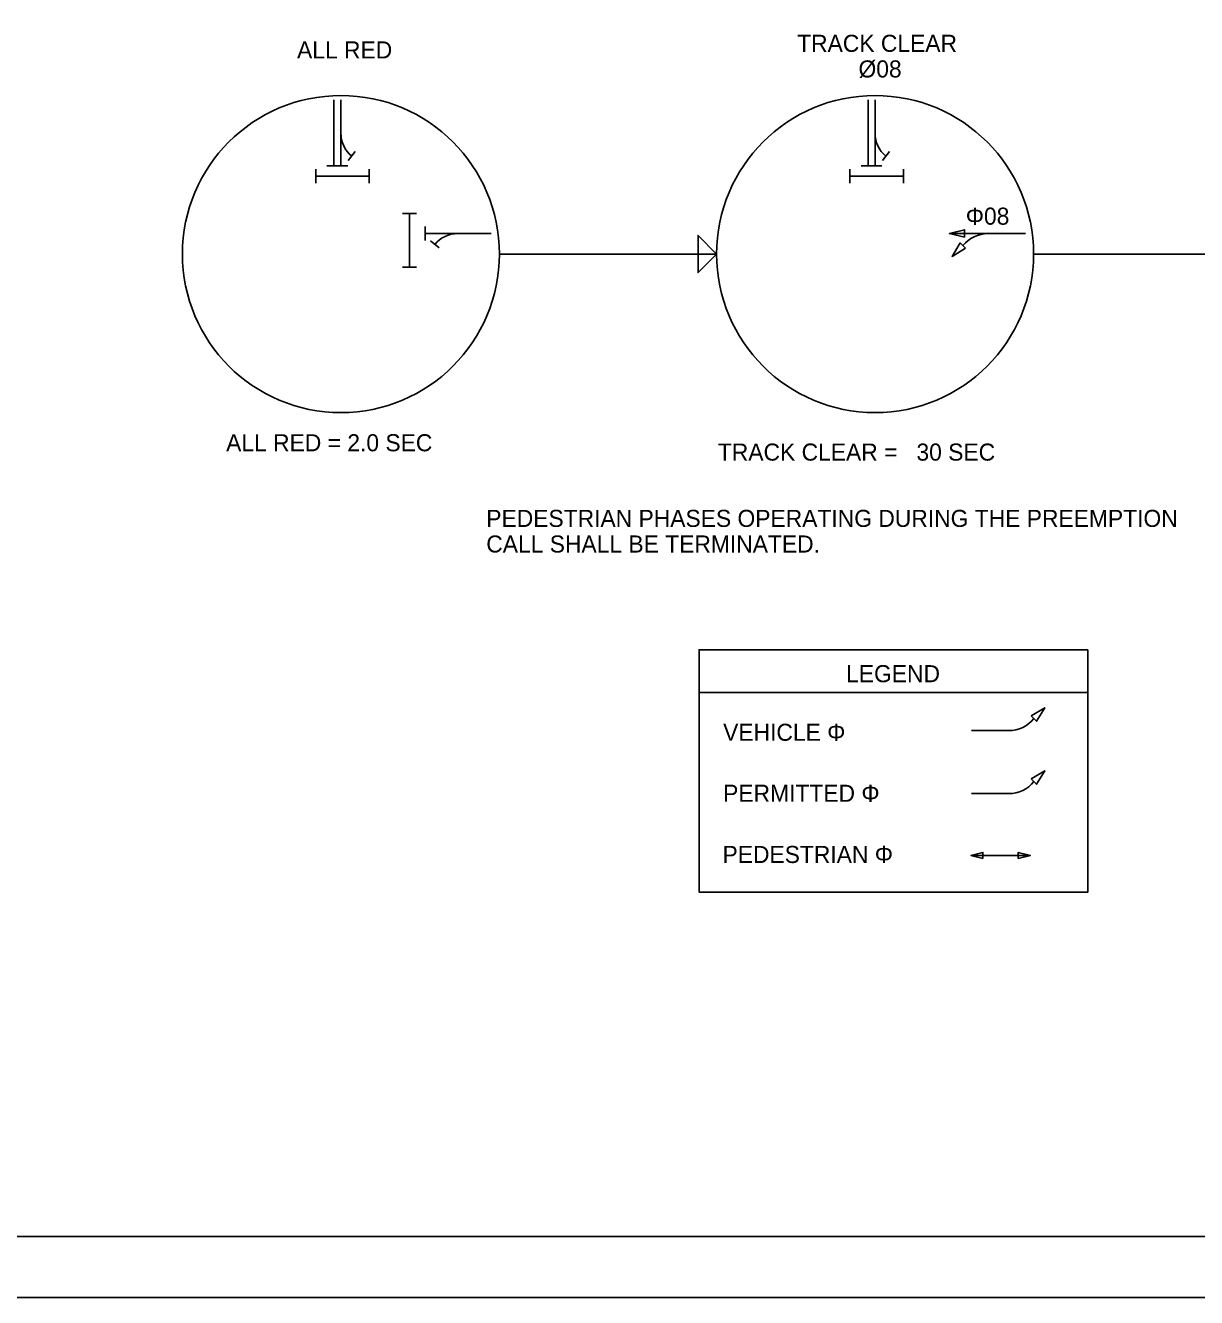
# Model space of a CAD drawing. Extents: x 0 to 680, y 0 to 440.
# Drawn here: x 340 to 532, y 0 to 208.6 of the extents above; entities that cross this region are included whole.
import ezdxf

# ---------------------------------------------------------------- set-up
doc = ezdxf.new("R2010")
doc.units = 0
for name, color, linetype in [('SG_P_Text', 7, 'Continuous'), ('SH_Border', 7, 'Continuous'), ('SH_Cut_Line', 7, 'Continuous'), ('SH_Data', 7, 'Continuous'), ('SH_Text', 7, 'Continuous')]:
    doc.layers.add(name, color=color, linetype=linetype)

msp = doc.modelspace()

# ---------------------------------------------------------------- linework, layer by layer
at = {"layer": 'SG_P_Text'}
for p, q in [((390.58, 196.38), (390.58, 185.57)), ((391.72, 196.38), (391.72, 185.57)), ((391.72, 196.38), (391.72, 190.88)), ((478.18, 196.38), (478.18, 185.57)), ((479.32, 196.38), (479.32, 185.57)), ((479.32, 196.38), (479.32, 190.88)), ((392.92, 186.45), (394.08, 187.88)), ((480.53, 186.45), (481.68, 187.88)), ((387.61, 184.99), (387.61, 182.71)), ((387.61, 183.85), (396.38, 183.85)), ((389.44, 185.57), (391.72, 185.57)), ((390.58, 185.57), (392.86, 185.57)), ((396.38, 184.99), (396.38, 182.71)), ((475.21, 184.99), (475.21, 182.71)), ((475.21, 183.85), (483.99, 183.85)), ((477.04, 185.57), (479.32, 185.57)), ((478.18, 185.57), (480.46, 185.57)), ((483.99, 184.99), (483.99, 182.71)), ((404.13, 177.71), (401.85, 177.71)), ((402.99, 168.93), (402.99, 177.71)), ((405.55, 173.31), (405.55, 175.59)), ((416.36, 174.45), (405.55, 174.45)), ((406.43, 173.25), (407.86, 172.09)), ((416.36, 174.45), (410.87, 174.45)), ((491.51, 174.45), (503.97, 174.45)), ((503.97, 174.45), (497.86, 174.45)), ((404.13, 168.93), (401.85, 168.93)), ((450.42, 99.22), (514.23, 99.22)), ((495.14, 92.95), (501.25, 92.96)), ((495.14, 82.62), (501.25, 82.62)), ((495.04, 72.48), (504.79, 72.48))]:
    msp.add_line(p, q, dxfattribs=at)
for points in [[(494.01, 173.83), (491.51, 174.45), (494.01, 175.08)], [(494.17, 172.03), (491.96, 170.71), (493.29, 172.91)], [(514.23, 106.22), (450.46, 106.22), (450.46, 66.47), (514.23, 66.47)], [(504.94, 95.38), (507.15, 96.7), (505.82, 94.49)], [(504.94, 85.04), (507.15, 86.36), (505.82, 84.15)], [(497.02, 71.98), (495.04, 72.48), (497.02, 72.97)], [(502.81, 71.98), (504.79, 72.48), (502.81, 72.97)]]:
    msp.add_lwpolyline(points, close=True, dxfattribs=at)
for centre in [(391.73, 171.09), (479.33, 171.09)]:
    msp.add_circle(centre, 25.99, dxfattribs=at)
for centre, radius, start, end in [((396.49, 190.88), 4.77, 180, 231.2007), ((484.09, 190.88), 4.77, 180, 231.2007), ((410.87, 169.68), 4.77, 90, 141.2007), ((497.86, 169.15), 5.3, 90, 141.2007), ((501.25, 98.26), 5.3, 270.0129, 321.2136), ((501.25, 87.92), 5.3, 270, 321.2007)]:
    msp.add_arc(centre, radius, start, end, dxfattribs=at)
at = {"layer": 'SH_Border'}
msp.add_lwpolyline([(30, 430), (670, 430), (670, 10), (30, 10)], close=True, dxfattribs=at)
at = {"layer": 'SH_Cut_Line'}
msp.add_lwpolyline([(0, 0), (680, 0), (680, 440), (0, 440)], close=True, dxfattribs=at)
at = {"layer": 'SH_Data'}
for p, q in [((453.34, 171.09), (417.72, 171.09)), ((540.94, 171.09), (505.32, 171.09))]:
    msp.add_line(p, q, dxfattribs=at)
msp.add_lwpolyline([(453.34, 171.09), (450.31, 174.13), (450.31, 168.06)], close=True, dxfattribs=at)

# ---------------------------------------------------------------- texts
at = {"layer": 'SG_P_Text'}
for s, p in [('Φ08', (494.2, 175.9)), ('PEDESTRIAN PHASES OPERATING DURING THE PREEMPTION', (415.57, 126.35)), ('CALL SHALL BE TERMINATED.', (415.57, 122.15)), ('LEGEND', (474.58, 100.89)), ('VEHICLE Φ', (454.41, 91.28)), ('PERMITTED Φ', (454.41, 81.28)), ('PEDESTRIAN Φ', (454.31, 71.25))]:
    msp.add_text(s, height=2.8, dxfattribs=at).set_placement(p)
at = {"layer": 'SH_Text'}
for s, p in [('TRACK CLEAR', (466.55, 204.24)), ('ALL RED', (384.54, 203.16)), ('Ø08', (476.61, 200.04)), ('ALL RED = 2.0 SEC', (372.91, 138.75)), ('TRACK CLEAR =   30 SEC', (453.55, 137.22))]:
    msp.add_text(s, height=2.8, dxfattribs=at).set_placement(p)

doc.saveas('drawing.dxf')
